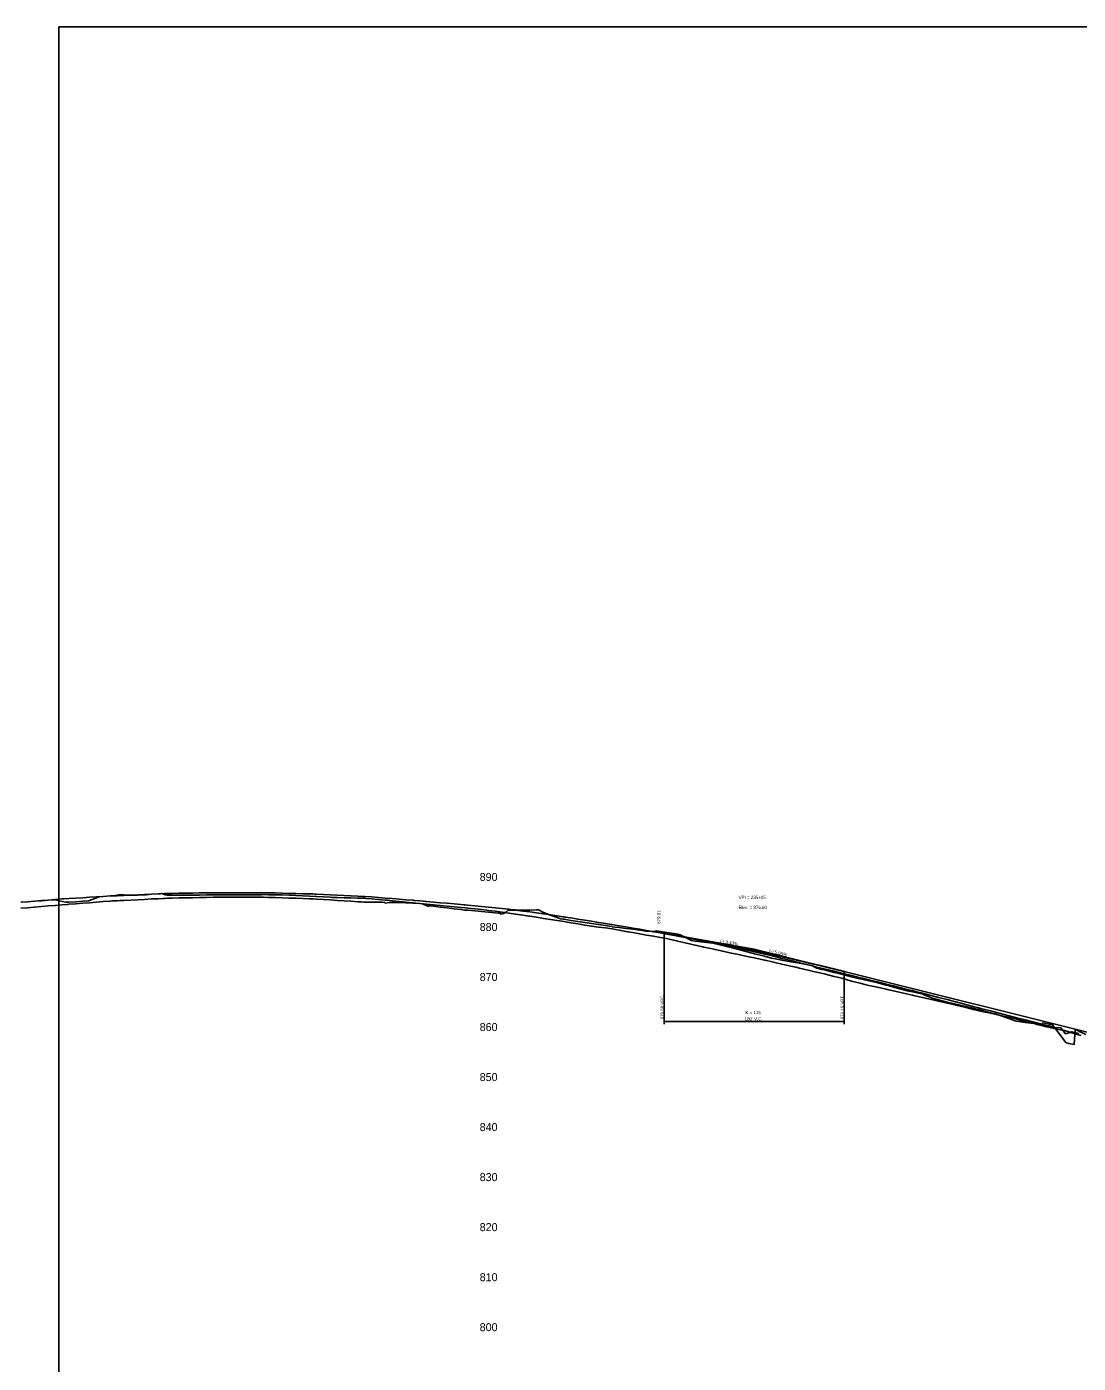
# Model space of a CAD drawing. Extents: x 1475945 to 1495590, y 1094511 to 1111511.
# Drawn here: x 1491831 to 1492882, y 1095730 to 1097066 of the extents above; entities that cross this region are included whole.
import ezdxf

# ---------------------------------------------------------------- set-up
doc = ezdxf.new("R2010")
doc.units = 0
for name, color, linetype in [('RD_DDB_ElevTX', 7, 'Continuous'), ('RD_DDB_GradeTX', 7, 'Continuous'), ('RD_DDB_Profile_EX', 7, 'Continuous'), ('RD_DDB_Profile_Lbl', 7, 'Continuous'), ('RD_DDB_Profile_PR', 7, 'Continuous'), ('RD_DDB_StripGrade', 7, 'Continuous'), ('RD_DDB_VCLbl', 7, 'Continuous'), ('RD_Sketch2', 7, 'Continuous'), ('RD_Sketch3', 7, 'Continuous'), ('RD_Sketch7', 7, 'Continuous')]:
    doc.layers.add(name, color=color, linetype=linetype)

msp = doc.modelspace()

# ---------------------------------------------------------------- linework, layer by layer
at = {"layer": 'RD_DDB_GradeTX'}
for p in [(1492477.1, 1096158.2), (1492638.2, 1096124.2)]:
    msp.add_line(p, (1492558.3, 1096144.2), dxfattribs=at)
at = {"layer": 'RD_DDB_Profile_EX'}
msp.add_lwpolyline([(1491825.2, 1096190.9), (1491832.1, 1096191.4), (1491839, 1096192), (1491845.9, 1096192.6), (1491852.7, 1096193.1), (1491859.6, 1096193.7), (1491866.5, 1096194.2), (1491868, 1096194.4), (1491868.4, 1096194.4), (1491873.4, 1096194.7), (1491880.2, 1096195.1), (1491887.1, 1096195.5), (1491894, 1096195.9), (1491900.8, 1096196.4), (1491907.7, 1096196.8), (1491914.6, 1096197.2), (1491918, 1096197.4), (1491918.5, 1096197.4), (1491921.5, 1096197.5), (1491928.3, 1096197.8), (1491935.2, 1096198.1), (1491942.1, 1096198.4), (1491949, 1096198.7), (1491955.8, 1096199), (1491962.7, 1096199.3), (1491968.8, 1096199.6), (1491969.6, 1096199.6), (1491976.5, 1096199.8), (1491983.3, 1096199.9), (1491990.2, 1096200), (1491997.1, 1096200.1), (1492003.9, 1096200.3), (1492010.8, 1096200.4), (1492017.7, 1096200.5), (1492018.8, 1096200.5), (1492024.6, 1096200.5), (1492031.4, 1096200.5), (1492038.3, 1096200.5), (1492045.2, 1096200.5), (1492052.1, 1096200.5), (1492058.9, 1096200.5), (1492065.8, 1096200.5), (1492066.7, 1096200.5), (1492068.8, 1096200.5), (1492072.7, 1096200.4), (1492079.6, 1096200.2), (1492086.4, 1096200), (1492093.3, 1096199.8), (1492100.2, 1096199.6), (1492107.1, 1096199.5), (1492113.9, 1096199.3), (1492117.2, 1096199.2), (1492119, 1096199.1), (1492120.8, 1096199), (1492127.7, 1096198.7), (1492134.5, 1096198.4), (1492141.4, 1096198.1), (1492148.3, 1096197.7), (1492155.2, 1096197.4), (1492162, 1096197.1), (1492167.6, 1096196.8), (1492169.1, 1096196.7), (1492175.8, 1096196.2), (1492182.7, 1096195.6), (1492189.5, 1096195.1), (1492196.4, 1096194.6), (1492203.3, 1096194), (1492210.2, 1096193.5), (1492217, 1096192.9), (1492218, 1096192.8), (1492219.2, 1096192.8), (1492223.9, 1096192.3), (1492230.8, 1096191.7), (1492237.6, 1096191.1), (1492244.5, 1096190.5), (1492251.4, 1096189.9), (1492258.3, 1096189.4), (1492265.1, 1096188.8), (1492268.3, 1096188.5), (1492269.3, 1096188.4), (1492272, 1096188.1), (1492278.9, 1096187.4), (1492285.8, 1096186.7), (1492292.6, 1096186), (1492299.5, 1096185.3), (1492306.4, 1096184.6), (1492313.3, 1096183.9), (1492317.1, 1096183.5), (1492319.1, 1096183.2), (1492320.1, 1096183.1), (1492327, 1096182.1), (1492333.9, 1096181.2), (1492340.7, 1096180.2), (1492347.6, 1096179.2), (1492354.5, 1096178.2), (1492361.4, 1096177.3), (1492367, 1096176.5), (1492368.2, 1096176.3), (1492369.3, 1096176.1), (1492375.1, 1096175.2), (1492382, 1096174.1), (1492388.9, 1096173), (1492395.7, 1096171.9), (1492402.6, 1096170.8), (1492409.5, 1096169.7), (1492415.7, 1096168.7), (1492416.4, 1096168.6), (1492419.3, 1096168.1), (1492423.2, 1096167.4), (1492430.1, 1096166.2), (1492437, 1096165), (1492443.8, 1096163.9), (1492450.7, 1096162.7), (1492457.6, 1096161.5), (1492464.5, 1096160.3), (1492465.9, 1096160.1), (1492469.2, 1096159.5), (1492473.2, 1096158.7), (1492481.8, 1096157.1), (1492490.5, 1096155.4), (1492499.2, 1096153.7), (1492507.9, 1096152.1), (1492516.6, 1096150.4), (1492517.8, 1096150.2), (1492519.3, 1096149.9), (1492525.3, 1096148.6), (1492533.9, 1096146.7), (1492542.6, 1096144.8), (1492551.3, 1096142.9), (1492560, 1096141), (1492564.3, 1096140), (1492568.7, 1096139.1), (1492569.3, 1096138.9), (1492577.4, 1096136.9), (1492586, 1096134.8), (1492594.7, 1096132.6), (1492603.4, 1096130.5), (1492612.1, 1096128.3), (1492617.6, 1096127), (1492619.6, 1096126.5), (1492620.8, 1096126.2), (1492629.5, 1096124.1), (1492638.1, 1096122), (1492646.8, 1096119.8), (1492655.5, 1096117.7), (1492664.2, 1096115.5), (1492666.4, 1096115), (1492668.6, 1096114.4), (1492670.5, 1096114), (1492672.9, 1096113.4), (1492681.6, 1096111.3), (1492690.2, 1096109.1), (1492698.9, 1096106.9), (1492707.6, 1096104.8), (1492715.5, 1096102.8), (1492716.3, 1096102.6), (1492718.1, 1096102.1), (1492720.2, 1096101.7), (1492720.5, 1096101.4), (1492725, 1096100.3), (1492733.7, 1096098.1), (1492742.4, 1096095.8), (1492751, 1096093.6), (1492759.3, 1096091.5), (1492759.7, 1096091.4), (1492768.4, 1096089), (1492769.3, 1096088.8), (1492777.1, 1096086.8), (1492782.4, 1096085.4), (1492785.8, 1096084.5), (1492794.5, 1096082.3), (1492803.1, 1096080), (1492811.8, 1096077.7), (1492819.5, 1096075.7), (1492820.5, 1096075.4), (1492827.6, 1096073.8), (1492829.2, 1096073.4), (1492837.9, 1096071.1), (1492846.6, 1096068.9), (1492855.2, 1096066.6), (1492858.9, 1096065.7), (1492863.9, 1096065.3), (1492865.1, 1096065.2), (1492869.4, 1096059.5), (1492872.6, 1096060.5), (1492875.8, 1096061.5), (1492881.3, 1096060.1), (1492882.8, 1096059.7)], dxfattribs=at)
at = {"layer": 'RD_DDB_Profile_PR'}
for p, q in [((1492464.5, 1096160.3), (1492468.3, 1096159.7)), ((1492648.3, 1096121.7), (1492953.3, 1096045.5))]:
    msp.add_line(p, q, dxfattribs=at)
msp.add_spline([(1492468.3, 1096159.7), (1492471.9, 1096159), (1492475.5, 1096158.4), (1492479.1, 1096157.8), (1492482.7, 1096157.1), (1492486.3, 1096156.5), (1492489.9, 1096155.9), (1492493.5, 1096155.2), (1492497.1, 1096154.5), (1492500.7, 1096153.9), (1492504.3, 1096153.2), (1492507.9, 1096152.5), (1492511.5, 1096151.8), (1492515.1, 1096151.2), (1492518.7, 1096150.5), (1492522.3, 1096149.8), (1492525.9, 1096149.1), (1492529.5, 1096148.3), (1492533.1, 1096147.6), (1492536.7, 1096146.9), (1492540.3, 1096146.2), (1492543.9, 1096145.4), (1492547.5, 1096144.7), (1492551.1, 1096144), (1492554.7, 1096143.2), (1492558.3, 1096142.5), (1492561.9, 1096141.7), (1492565.5, 1096140.9), (1492569.1, 1096140.2), (1492572.7, 1096139.4), (1492576.3, 1096138.6), (1492579.9, 1096137.8), (1492583.5, 1096137), (1492587.1, 1096136.2), (1492590.7, 1096135.4), (1492594.3, 1096134.6), (1492597.9, 1096133.8), (1492601.5, 1096132.9), (1492605.1, 1096132.1), (1492608.7, 1096131.3), (1492612.3, 1096130.4), (1492615.9, 1096129.6), (1492619.5, 1096128.7), (1492623.1, 1096127.9), (1492626.7, 1096127), (1492630.3, 1096126.2), (1492633.9, 1096125.3), (1492637.5, 1096124.4), (1492641.1, 1096123.5), (1492644.7, 1096122.6), (1492648.3, 1096121.7)], degree=3, dxfattribs=at)
at = {"layer": 'RD_DDB_VCLbl'}
for p, q in [((1492468.3, 1096069.2), (1492468.3, 1096159.7)), ((1492648.3, 1096069.2), (1492648.3, 1096121.7)), ((1492468.3, 1096071.7), (1492648.3, 1096071.7))]:
    msp.add_line(p, q, dxfattribs=at)
at = {"layer": 'RD_Sketch2'}
msp.add_lwpolyline([(1491826.2, 1096190.9), (1491832.1, 1096191.4), (1491839, 1096191.9), (1491845.9, 1096192.4), (1491852.7, 1096192.9), (1491859.1, 1096193.4), (1491859.6, 1096193.3), (1491866.5, 1096191.7), (1491870.2, 1096190.9), (1491873.4, 1096191.1), (1491880.2, 1096191.5), (1491887.1, 1096192), (1491892.9, 1096192.4), (1491894, 1096192.8), (1491900.8, 1096195.4), (1491903.4, 1096196.4), (1491907.7, 1096196.8), (1491914.6, 1096197.4), (1491919.9, 1096197.8), (1491921.5, 1096198.1), (1491923.3, 1096198.3), (1491923.8, 1096198.3), (1491925.4, 1096198.4), (1491928.3, 1096198.3), (1491935.2, 1096198.1), (1491939.3, 1096198), (1491942.1, 1096198.1), (1491949, 1096198.4), (1491950.4, 1096198.5), (1491955.8, 1096198.9), (1491962.7, 1096199.3), (1491965, 1096199.5), (1491966.2, 1096199.7), (1491968.9, 1096198.6), (1491969.6, 1096198.4), (1491971.7, 1096197.9), (1491976.5, 1096197.9), (1491983.3, 1096198), (1491990.2, 1096198), (1491996.7, 1096198.1), (1491997.1, 1096198.1), (1492003.9, 1096198.1), (1492010.8, 1096198.2), (1492017.7, 1096198.3), (1492020.3, 1096198.3), (1492024.6, 1096198.3), (1492031.4, 1096198.2), (1492038.3, 1096198.2), (1492042.4, 1096198.2), (1492045.2, 1096198.2), (1492052.1, 1096198.3), (1492058.9, 1096198.4), (1492065.8, 1096198.5), (1492070.3, 1096198.6), (1492072.7, 1096198.5), (1492079.6, 1096198.4), (1492086.4, 1096198.2), (1492093.3, 1096198.1), (1492094, 1096198), (1492100.2, 1096197.7), (1492107.1, 1096197.4), (1492113.9, 1096197), (1492120.2, 1096196.7), (1492120.8, 1096196.7), (1492127.7, 1096196.3), (1492134.5, 1096195.9), (1492136.2, 1096195.8), (1492141.4, 1096195.6), (1492148.3, 1096195.4), (1492155.2, 1096195.2), (1492162, 1096195), (1492168.9, 1096194.9), (1492170, 1096194.8), (1492175.8, 1096194.3), (1492182.7, 1096193.7), (1492189.5, 1096193.1), (1492191.8, 1096192.9), (1492196.4, 1096192.4), (1492203.3, 1096191.8), (1492210.2, 1096191.1), (1492217, 1096190.4), (1492220.1, 1096190.1), (1492223.9, 1096189.8), (1492230.8, 1096189.1), (1492237.6, 1096188.4), (1492244.5, 1096187.7), (1492251.4, 1096187.1), (1492258.3, 1096186.4), (1492265.1, 1096185.7), (1492269.8, 1096185.3), (1492272, 1096185), (1492278.9, 1096184.3), (1492285.8, 1096183.6), (1492290.9, 1096183.1), (1492292.6, 1096182.8), (1492299.5, 1096181.9), (1492306.4, 1096180.9), (1492313.3, 1096180), (1492319.6, 1096179.1), (1492320.1, 1096179.1), (1492327, 1096178), (1492333.1, 1096177.1), (1492333.9, 1096177), (1492340.7, 1096175.9), (1492347.6, 1096174.8), (1492354.5, 1096173.7), (1492361.4, 1096172.7), (1492368.2, 1096171.6), (1492369.5, 1096171.4), (1492375.1, 1096170.4), (1492382, 1096169.2), (1492385.8, 1096168.6), (1492388.9, 1096168.1), (1492395.7, 1096167.1), (1492402.6, 1096166.1), (1492409.5, 1096165.2), (1492416.4, 1096164.2), (1492419.5, 1096163.8), (1492423.2, 1096163.1), (1492430.1, 1096161.8), (1492432.1, 1096161.5), (1492437, 1096160.6), (1492443.8, 1096159.4), (1492450.7, 1096158.1), (1492457.6, 1096156.9), (1492464.5, 1096155.7), (1492469.2, 1096154.9), (1492473.2, 1096154), (1492481.8, 1096152), (1492490.5, 1096150), (1492499.2, 1096148), (1492506.8, 1096146.3), (1492507.9, 1096146), (1492516.6, 1096144.3), (1492519.2, 1096143.7), (1492525.3, 1096142.4), (1492532.6, 1096140.7), (1492533.9, 1096140.4), (1492542.6, 1096138.6), (1492551.3, 1096136.8), (1492560, 1096135), (1492568.7, 1096133.2), (1492569.1, 1096133.1), (1492577.4, 1096131.2), (1492586, 1096129.1), (1492594.7, 1096127.1), (1492600, 1096125.9), (1492603.4, 1096125.1), (1492612.1, 1096123.1), (1492618.8, 1096121.5), (1492620.8, 1096121.1), (1492629.5, 1096118.9), (1492638.1, 1096116.8), (1492641.5, 1096116), (1492646.8, 1096114.6), (1492655.5, 1096112.2), (1492664.2, 1096109.9), (1492668.9, 1096108.7), (1492672.9, 1096107.8), (1492681.6, 1096105.9), (1492690.2, 1096104), (1492691, 1096103.8), (1492698.9, 1096101.9), (1492707.6, 1096099.9), (1492716.3, 1096097.9), (1492718.7, 1096097.4), (1492725, 1096096), (1492733.7, 1096094), (1492742.4, 1096092), (1492751, 1096090.1), (1492759, 1096088.3), (1492759.7, 1096088.1), (1492768.4, 1096086.1), (1492768.7, 1096086.1), (1492774.8, 1096084.3), (1492777.1, 1096083.8), (1492785.8, 1096081.9), (1492794.5, 1096080), (1492803.1, 1096078.1), (1492811.8, 1096076.2), (1492814, 1096075.7), (1492818.1, 1096074.7), (1492818.6, 1096074.6), (1492820.5, 1096074.1), (1492829.2, 1096071.9), (1492837.9, 1096069.6), (1492843.9, 1096068.1), (1492846.6, 1096067.4), (1492850.3, 1096066.5), (1492854, 1096065.6), (1492855.2, 1096065.3), (1492857.9, 1096064.6), (1492863.9, 1096063.5), (1492868.5, 1096062.7), (1492872.6, 1096061.4), (1492880.9, 1096058.9), (1492881.3, 1096058.8), (1492885.1, 1096057.8)], dxfattribs=at)
at = {"layer": 'RD_Sketch3'}
msp.add_lwpolyline([(1491825.2, 1096184.9), (1491832.1, 1096185.5), (1491839, 1096186), (1491845.9, 1096186.6), (1491852.7, 1096187.2), (1491859.6, 1096187.7), (1491866.5, 1096188.3), (1491871.9, 1096188.8), (1491873.4, 1096188.9), (1491880.2, 1096189.5), (1491887.1, 1096190), (1491894, 1096190.5), (1491900.8, 1096191), (1491907.7, 1096191.6), (1491914.6, 1096192.1), (1491916.8, 1096192.2), (1491921.5, 1096192.5), (1491924.6, 1096192.6), (1491928.3, 1096192.8), (1491935.2, 1096193.1), (1491942.1, 1096193.5), (1491949, 1096193.8), (1491955.8, 1096194.2), (1491962.7, 1096194.5), (1491967.1, 1096194.7), (1491969.6, 1096194.8), (1491971.8, 1096195), (1491976.5, 1096195.1), (1491983.3, 1096195.2), (1491990.2, 1096195.4), (1491997.1, 1096195.5), (1492003.9, 1096195.7), (1492010.8, 1096195.8), (1492017.4, 1096196), (1492017.7, 1096196), (1492021.6, 1096196), (1492024.6, 1096196), (1492031.4, 1096196), (1492038.3, 1096196), (1492045.2, 1096196), (1492052.1, 1096196), (1492057.2, 1096196), (1492058.9, 1096196), (1492065.8, 1096195.9), (1492067.3, 1096195.9), (1492067.7, 1096195.9), (1492072.7, 1096195.8), (1492079.6, 1096195.6), (1492086.4, 1096195.3), (1492093.3, 1096195.1), (1492100.2, 1096194.9), (1492107.1, 1096194.7), (1492113.9, 1096194.4), (1492116, 1096194.4), (1492117.9, 1096194.3), (1492120.8, 1096194.1), (1492127.7, 1096193.7), (1492134.5, 1096193.3), (1492141.4, 1096192.8), (1492148.3, 1096192.4), (1492155.2, 1096191.9), (1492162, 1096191.5), (1492165.6, 1096191.2), (1492168.2, 1096191.1), (1492168.9, 1096191.1), (1492175.8, 1096191), (1492182.7, 1096191), (1492186.4, 1096190.9), (1492189, 1096190.7), (1492189.5, 1096190.1), (1492193.6, 1096190.6), (1492196.4, 1096190.7), (1492198.1, 1096190.8), (1492203.3, 1096190.6), (1492210.2, 1096190.2), (1492217, 1096189.9), (1492223.9, 1096189.6), (1492226.7, 1096189.5), (1492230.3, 1096187.8), (1492230.8, 1096187.6), (1492233, 1096186.7), (1492233, 1096187.4), (1492235.2, 1096187.2), (1492237.6, 1096186.9), (1492244.5, 1096186.1), (1492251.4, 1096185.3), (1492258.3, 1096184.4), (1492265.1, 1096183.6), (1492268.7, 1096183.1), (1492272, 1096182.9), (1492278.9, 1096182.2), (1492285.8, 1096181.6), (1492292.6, 1096181), (1492299.5, 1096180.4), (1492303.1, 1096180.1), (1492304.8, 1096179.9), (1492305, 1096179.1), (1492306.4, 1096179.4), (1492307.8, 1096179.8), (1492310.8, 1096181.5), (1492312.4, 1096182.9), (1492313.3, 1096182.9), (1492320.1, 1096183), (1492327, 1096183.1), (1492333.9, 1096183.1), (1492340.7, 1096183.2), (1492342.5, 1096183.2), (1492347.6, 1096180.7), (1492348.6, 1096180.2), (1492354.5, 1096178.1), (1492361.4, 1096175.6), (1492364.6, 1096174.4), (1492367.2, 1096174), (1492368.2, 1096173.9), (1492375.1, 1096172.8), (1492382, 1096171.8), (1492388.9, 1096170.7), (1492395.7, 1096169.7), (1492402.6, 1096168.6), (1492409.5, 1096167.6), (1492415.9, 1096166.6), (1492416.4, 1096166.5), (1492419.1, 1096166.1), (1492423.2, 1096165.6), (1492430.1, 1096164.7), (1492437, 1096163.9), (1492443.8, 1096163), (1492446.5, 1096162.7), (1492449.9, 1096162.1), (1492450.7, 1096162), (1492456.4, 1096161.6), (1492457.6, 1096161.8), (1492460.8, 1096162.3), (1492464.5, 1096161.7), (1492473.2, 1096160.3), (1492481.8, 1096158.9), (1492484.3, 1096158.5), (1492490.5, 1096155.3), (1492491.6, 1096154.7), (1492495.5, 1096152.8), (1492499.2, 1096152.1), (1492507.9, 1096151), (1492516.8, 1096149.9), (1492525.3, 1096147.9), (1492531.8, 1096146.5), (1492532.1, 1096146.4), (1492533.5, 1096146.1), (1492533.9, 1096145.9), (1492542.6, 1096143.7), (1492551.3, 1096141.4), (1492560, 1096139.2), (1492568.7, 1096136.9), (1492569.4, 1096136.7), (1492575.6, 1096134.9), (1492577.4, 1096134.6), (1492586, 1096133.1), (1492594.7, 1096131.5), (1492603.4, 1096129.9), (1492612.1, 1096128.4), (1492615.9, 1096127.7), (1492618.1, 1096126.3), (1492619.4, 1096125.6), (1492620.8, 1096125.2), (1492625.9, 1096123.8), (1492628.2, 1096123.3), (1492629.5, 1096123), (1492638.1, 1096120.8), (1492640, 1096120.4), (1492646.8, 1096118.7), (1492655.5, 1096116.5), (1492662.1, 1096114.8), (1492664.2, 1096114.3), (1492672.9, 1096112.3), (1492681.8, 1096110.3), (1492690.2, 1096108.2), (1492693.2, 1096107.4), (1492698.9, 1096105.8), (1492707.6, 1096103.3), (1492711.1, 1096102.3), (1492716.3, 1096101.3), (1492724.1, 1096099.8), (1492725, 1096099.6), (1492725.7, 1096099.6), (1492726, 1096099.5), (1492728.1, 1096098.5), (1492733.7, 1096096.2), (1492736.2, 1096095.2), (1492742.4, 1096093.5), (1492751, 1096091.2), (1492752.5, 1096090.8), (1492759.7, 1096089), (1492768.4, 1096086.9), (1492770, 1096086.6), (1492772.7, 1096086.2), (1492777.1, 1096084.9), (1492785.8, 1096082.7), (1492794.5, 1096080.5), (1492799.2, 1096079.3), (1492803.1, 1096078), (1492811.8, 1096075), (1492820, 1096072.2), (1492820.5, 1096072.1), (1492829.2, 1096070.9), (1492838.1, 1096069.7), (1492839.5, 1096069.3), (1492840.7, 1096068.6), (1492845.3, 1096067.6), (1492846.6, 1096070.3), (1492850, 1096069.6), (1492853.1, 1096069), (1492853.9, 1096068.8), (1492855.2, 1096068.7), (1492856.2, 1096068.7), (1492863.9, 1096058.5), (1492869.5, 1096051.2), (1492870.3, 1096050.3), (1492872.6, 1096049.9), (1492878.2, 1096048.9), (1492879.2, 1096063.6), (1492880.2, 1096063.3), (1492881.3, 1096062.8), (1492889.8, 1096058.7)], dxfattribs=at)
at = {"layer": 'RD_Sketch7'}
msp.add_lwpolyline([(1491863.3, 1094866), (1495463.3, 1094866), (1495463.3, 1097066), (1491863.3, 1097066)], close=True, dxfattribs=at)

# ---------------------------------------------------------------- texts
at = {"layer": 'RD_DDB_ElevTX'}
for s, p in [('890', (1492283.9, 1096212.2)), ('880', (1492283.9, 1096162.2)), ('870', (1492283.9, 1096112.2)), ('860', (1492283.9, 1096062.2)), ('850', (1492283.9, 1096012.2)), ('840', (1492283.9, 1095962.2)), ('830', (1492283.9, 1095912.2)), ('820', (1492283.9, 1095862.2)), ('810', (1492283.9, 1095812.2)), ('800', (1492283.9, 1095762.2))]:
    msp.add_text(s, height=8, dxfattribs=at).set_placement(p)
at = {"layer": 'RD_DDB_GradeTX'}
for s, rotation, p in [('(-) 3.43%', 350.2684, (1492523.8, 1096150.6)), ('(-) 5.00%', 345.9638, (1492572.9, 1096141.1))]:
    msp.add_text(s, height=3.2, rotation=rotation, dxfattribs=at).set_placement(p)
at = {"layer": 'RD_DDB_Profile_Lbl'}
for s, p in [('VPI = 235+95', (1492542.7, 1096194.2)), ('Elev. = 876.60', (1492542.6, 1096184.2))]:
    msp.add_text(s, height=3.2, dxfattribs=at).set_placement(p)
msp.add_text('879.81', height=3.2, rotation=90, dxfattribs=at).set_placement((1492464.5, 1096169.3))
at = {"layer": 'RD_DDB_StripGrade'}
for s, p in [('879.68 VPC', (1492467.9, 1096073.9)), ('872.10 VPT', (1492647.9, 1096073.9))]:
    msp.add_text(s, height=3.2, rotation=90, dxfattribs=at).set_placement(p)
at = {"layer": 'RD_DDB_VCLbl'}
for s, p in [("180' V.C.", (1492548.7, 1096072.7)), ('K = 115', (1492549.5, 1096079.1))]:
    msp.add_text(s, height=3.2, dxfattribs=at).set_placement(p)

doc.saveas('drawing.dxf')
